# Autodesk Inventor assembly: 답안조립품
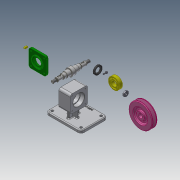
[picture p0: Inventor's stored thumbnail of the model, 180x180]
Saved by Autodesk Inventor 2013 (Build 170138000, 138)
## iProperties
Created: 2020-11
Part Number: 답안조립품
Document SubType Name: Assembly
Designer: 19
Author: 19
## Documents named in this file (10)
- C:\Users\user\Desktop\701106V1012\답안조립품.iam
- C:\Users\user\Desktop\701106V1012\본체.ipt
- C:\Users\user\Desktop\701106V1012\V-벨트풀리.ipt
- C:\Users\user\Desktop\701106V1012\너트 M10x1.ipt
- C:\Users\user\Desktop\701106V1012\베어링 6004.ipt
- C:\Users\user\Desktop\701106V1012\볼트 M4.ipt
- C:\Users\user\Desktop\701106V1012\오일 실 17 30 5.ipt
- C:\Users\user\Desktop\701106V1012\축.ipt
- C:\Users\user\Desktop\701106V1012\커버.ipt
- C:\Users\user\Desktop\701106V1012\키 5 x 5 x 12.ipt
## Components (1 placed, 1 different names)
1. V-벨트풀리:1
